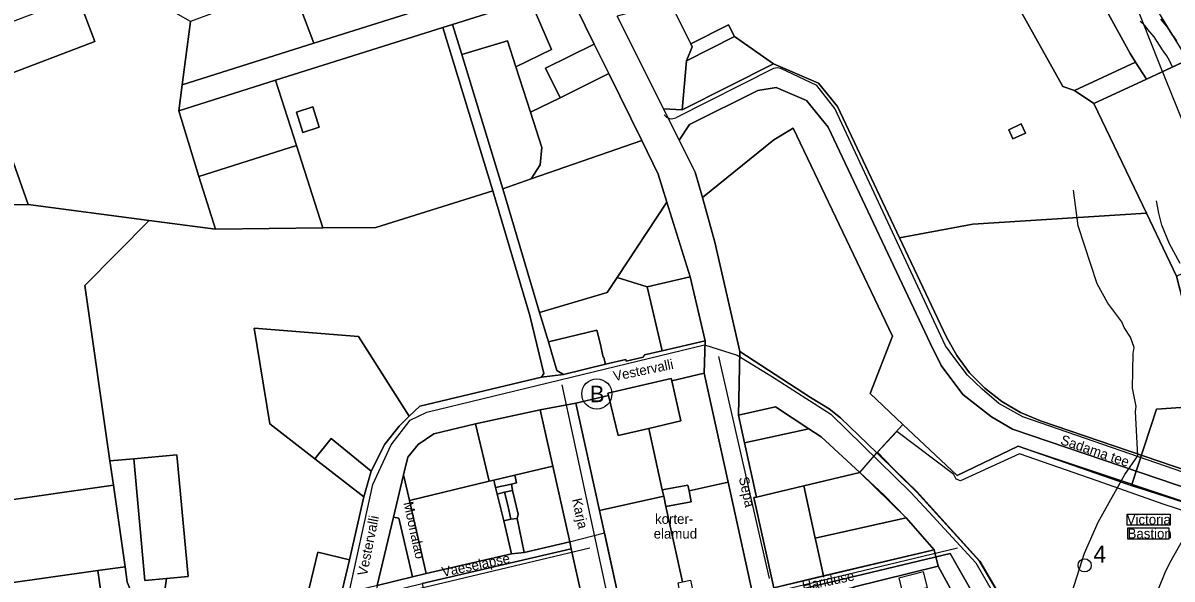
# Model space of a CAD drawing. Extents: x 728832 to 739469, y 6586263 to 6599699.
# Drawn here: x 738162 to 738859, y 6590082 to 6590420 of the extents above; entities that cross this region are included whole.
import ezdxf

# ---------------------------------------------------------------- set-up
doc = ezdxf.new("R2010")
doc.units = 0
for name, color, linetype in [('_olol_kinnismalestis', 7, 'Continuous'), ('a_kalda_ekv', 7, 'Continuous'), ('a_kalda_piiranguv', 7, 'Continuous'), ('a_kalda_veekaitsev', 7, 'Continuous'), ('a_looduskaitse_voond', 7, 'Continuous'), ('a_piir', 7, 'Continuous'), ('a_veekogu_piir', 7, 'Continuous'), ('dp_hoonestus', 7, 'Continuous'), ('PIIR', 7, 'Continuous'), ('v_dp_kehtiv', 7, 'Continuous'), ('v_dp_kontaktvoond', 7, 'Continuous'), ('v_dp_situatsioon_tekst', 7, 'Continuous'), ('v_dp_tanav_tekst', 7, 'Continuous'), ('v_dp_tekst', 7, 'Continuous'), ('v_dp_transp_bussipeatus', 7, 'Continuous'), ('v_olol_transp_jjt', 7, 'Continuous')]:
    doc.layers.add(name, color=color, linetype=linetype)

msp = doc.modelspace()

# ---------------------------------------------------------------- linework, layer by layer
at = {"layer": '_olol_kinnismalestis'}
msp.add_circle((738805.8, 6590090.62), 4, dxfattribs=at)
at = {"layer": 'a_kalda_ekv'}
for points in [[(738863.76, 6590273.78), (738857.24, 6590285.58), (738852.66, 6590296.98), (738850.77, 6590304.13), (738849.38, 6590311.72)], [(738850.77, 6590076.81), (738854.63, 6590086.37), (738857.47, 6590092.24), (738873.8, 6590121.13)]]:
    msp.add_lwpolyline(points, dxfattribs=at)
at = {"layer": 'a_kalda_piiranguv'}
msp.add_lwpolyline([(738798, 6590073.89), (738805.74, 6590098.09), (738813.94, 6590116.85), (738830.28, 6590145.74), (738838.07, 6590157), (738836.66, 6590184.02), (738837, 6590187.05), (738834.95, 6590198.11), (738835.2, 6590219.08), (738835.91, 6590222.7), (738833.64, 6590229.08), (738829.85, 6590234.96), (738828.33, 6590238.38), (738819.99, 6590249.6), (738813.47, 6590261.4), (738801.89, 6590296.47), (738798.99, 6590318.06)], dxfattribs=at)
at = {"layer": 'a_kalda_veekaitsev'}
for points in [[(738851.97, 6590421.95), (738855.98, 6590417.06), (738858.79, 6590412.67), (738861.49, 6590408.69)], [(738858.97, 6590393.1), (738857.23, 6590396.81), (738855.69, 6590399.72), (738853.45, 6590402.75), (738853.34, 6590402.9), (738853.23, 6590403.05), (738853.13, 6590403.2), (738847.92, 6590411.12), (738844.24, 6590415.6), (738842.52, 6590417.91), (738841.51, 6590418.9), (738839.59, 6590420.47)]]:
    msp.add_lwpolyline(points, dxfattribs=at)
at = {"layer": 'a_looduskaitse_voond'}
msp.add_lwpolyline([(738894.43, 6590114.34), (738853.38, 6590127.75), (738813.33, 6590141.82), (738766.33, 6590158.2), (738730.58, 6590141.98), (738727.93, 6590142.81), (738726.44, 6590145.79), (738691.85, 6590171.77), (738680.1, 6590159.36), (738689.37, 6590149.76), (738697.97, 6590141.32), (738703.93, 6590135.69), (738742.33, 6590093.16), (738753.42, 6590074.13)], dxfattribs=at)
for points in [[(738831.57, 6590121.69), (738857.79, 6590121.69), (738857.79, 6590114.98), (738831.57, 6590114.98)], [(738832.11, 6590113.33), (738856.97, 6590113.33), (738856.97, 6590106.43), (738832.11, 6590106.43)]]:
    msp.add_lwpolyline(points, close=True, dxfattribs=at)
at = {"layer": 'a_piir'}
for points in [[(738714.39, 6590648.68), (738701.09, 6590633.5), (738709.17, 6590600.23), (738724.9, 6590576.43), (738753.65, 6590521.22), (738764.74, 6590499.89), (738777.5, 6590495.02), (738782.96, 6590492.93), (738797.98, 6590465.61), (738833.44, 6590401.09), (738836.76, 6590395.87), (738843.38, 6590385.47), (738861.23, 6590393.76), (738868.42, 6590397.1), (738805.45, 6590500.11), (738796.89, 6590523.24), (738791.68, 6590528.96), (738769.71, 6590541.44), (738762.96, 6590546.51), (738751.84, 6590562.22), (738726.66, 6590613.29), (738725.19, 6590623.95)], [(738348.19, 6590560.75), (738361.16, 6590523.06), (738302.71, 6590501.98), (738324.83, 6590443.26), (738338.39, 6590407.26), (738443.88, 6590440.57), (738429.88, 6590478.4), (738419.06, 6590507.64), (738408.21, 6590535.58), (738396.36, 6590567.69), (738396.18, 6590568.2), (738392.91, 6590567.08), (738374.34, 6590560.23), (738371.16, 6590569.04)], [(738182.4, 6590516.09), (738166.83, 6590510.19), (738205.45, 6590408.26), (738139.06, 6590383.11), (738165.15, 6590309.38), (738238.5, 6590299.83), (738278.68, 6590294.6), (738268.68, 6590326.48), (738256.37, 6590366.25), (738258.43, 6590382), (738263.45, 6590420.38), (738211.78, 6590450.22), (738206.1, 6590465.17), (738201.97, 6590463.62)], [(738166.83, 6590510.19), (738153.74, 6590505.23), (738182.08, 6590430.42), (738107.28, 6590402.08), (738112.93, 6590387.16), (738139.06, 6590383.11), (738205.45, 6590408.26)], [(738658.61, 6590458.95), (738548, 6590444.85), (738554.28, 6590432.27), (738566.99, 6590406.83), (738589.9, 6590418.44), (738593.51, 6590411.34), (738617.06, 6590394.78), (738644.37, 6590383.07), (738655.92, 6590368.86), (738693.54, 6590289.26), (738738, 6590297.5), (738843.25, 6590304.19), (738811.42, 6590370.68), (738799.59, 6590378.66), (738792.6, 6590380.94), (738757.76, 6590443.5), (738743.61, 6590468.92), (738713.5, 6590459.56), (738683.62, 6590450.33), (738672.4, 6590481.35)], [(738797.98, 6590465.61), (738757.76, 6590443.5), (738792.6, 6590380.94), (738799.59, 6590378.66), (738836.76, 6590395.87), (738833.44, 6590401.09)], [(738443.88, 6590440.57), (738338.39, 6590407.26), (738258.43, 6590382), (738256.37, 6590366.25), (738315.06, 6590384.77), (738416.58, 6590416.85), (738422.48, 6590418.71), (738469.63, 6590433.6), (738491.73, 6590440.58), (738485.29, 6590453.65)], [(738263.45, 6590420.38), (738258.43, 6590382), (738338.39, 6590407.26), (738324.83, 6590443.26)], [(738469.7, 6590365.38), (738487.64, 6590374.22), (738478.8, 6590392.17), (738508.39, 6590406.75), (738491.73, 6590440.58), (738469.63, 6590433.6), (738482.43, 6590403.56), (738460.89, 6590392.94)], [(738469.63, 6590433.6), (738422.48, 6590418.71), (738428.13, 6590400.35), (738455.82, 6590408.79), (738460.89, 6590392.94), (738482.43, 6590403.56)], [(738554.28, 6590432.27), (738522.36, 6590423.74), (738550.42, 6590367.55), (738561.68, 6590366.87), (738564.37, 6590396.51), (738567.87, 6590405.02), (738566.99, 6590406.83)], [(738416.58, 6590416.85), (738315.06, 6590384.77), (738327.82, 6590345.21), (738343.89, 6590295.31), (738375.96, 6590295.57), (738446.82, 6590317.75)], [(738422.48, 6590418.71), (738416.58, 6590416.85), (738446.82, 6590317.75), (738469.35, 6590242.13), (738477.74, 6590206.88), (738476.47, 6590204.81), (738489.66, 6590206.4), (738485.74, 6590208.8), (738480.57, 6590226.15), (738475.29, 6590243.89), (738452.88, 6590319.06), (738428.13, 6590400.35)], [(738567.87, 6590405.02), (738564.37, 6590396.51), (738593.51, 6590411.34), (738589.9, 6590418.44), (738566.99, 6590406.83)], [(738455.82, 6590408.79), (738428.13, 6590400.35), (738452.88, 6590319.06), (738470.12, 6590325.05), (738475.52, 6590333.61), (738476.53, 6590344.05), (738469.7, 6590365.38), (738460.89, 6590392.94)], [(738593.51, 6590411.34), (738564.37, 6590396.51), (738561.68, 6590366.87), (738617.06, 6590394.78)], [(738508.39, 6590406.75), (738478.8, 6590392.17), (738487.64, 6590374.22), (738517.23, 6590388.81)], [(738799.59, 6590378.66), (738811.42, 6590370.68), (738843.38, 6590385.47), (738836.76, 6590395.87)], [(738868.42, 6590397.1), (738861.23, 6590393.76), (738843.38, 6590385.47), (738811.42, 6590370.68), (738843.25, 6590304.19), (738861.55, 6590265.91), (738879.95, 6590274.65), (738893.72, 6590281.43), (738909.55, 6590289.44), (738899.03, 6590318.58), (738896.01, 6590344.11), (738886.01, 6590366.86)], [(738112.93, 6590387.16), (738024.66, 6590353.6), (738028.04, 6590344.14), (738032.7, 6590309.07), (738165.15, 6590309.38), (738139.06, 6590383.11)], [(738487.64, 6590374.22), (738469.7, 6590365.38), (738476.53, 6590344.05), (738475.52, 6590333.61), (738470.12, 6590325.05), (738537.19, 6590348.31), (738517.23, 6590388.81)], [(738315.06, 6590384.77), (738256.37, 6590366.25), (738268.68, 6590326.48), (738327.82, 6590345.21)], [(738618.75, 6590380.33), (738607.64, 6590378.6), (738566.13, 6590357.93), (738559.92, 6590348.55), (738569.64, 6590329.09), (738573.98, 6590313.62), (738617.27, 6590348.72), (738629.02, 6590355.8), (738689.32, 6590229.61), (738675.68, 6590194.79), (738695.6, 6590176.04), (738728.46, 6590145.13), (738765.47, 6590163.01), (738835.3, 6590138.74), (738883.93, 6590123.77), (738901.84, 6590117.49), (738905.68, 6590124.48), (738762.03, 6590173.28), (738749.36, 6590180.65), (738732, 6590194.18), (738718.81, 6590211.81), (738712.34, 6590224.93), (738650.22, 6590356.38), (738637.19, 6590372.44)], [(738337.76, 6590368.7), (738341.61, 6590356.44), (738331.63, 6590353.22), (738327.77, 6590365.48)], [(738337.76, 6590368.7), (738327.77, 6590365.48), (738331.63, 6590353.22), (738341.61, 6590356.44)], [(738629.02, 6590355.8), (738617.27, 6590348.72), (738573.98, 6590313.62), (738581.58, 6590286.62), (738596.71, 6590220.35), (738639.48, 6590192.38), (738650.86, 6590185.59), (738657.67, 6590180.09), (738679.71, 6590158.82), (738695.6, 6590176.04), (738675.68, 6590194.79), (738689.32, 6590229.61)], [(738767.41, 6590358.32), (738769.94, 6590352.81), (738762.33, 6590349.3), (738759.8, 6590354.82)], [(738767.41, 6590358.32), (738759.8, 6590354.82), (738762.33, 6590349.3), (738769.94, 6590352.81)], [(738537.19, 6590348.31), (738470.12, 6590325.05), (738452.88, 6590319.06), (738475.29, 6590243.89), (738516.31, 6590256.12), (738522.25, 6590265.1), (738552.48, 6590310.81), (738547.27, 6590327.85)], [(738327.82, 6590345.21), (738268.68, 6590326.48), (738278.68, 6590294.6), (738343.89, 6590295.31)], [(738552.48, 6590310.81), (738522.25, 6590265.1), (738540.46, 6590259.57), (738566.52, 6590265.62)], [(738032.7, 6590309.07), (738040.91, 6590247.3), (738113.13, 6590254.89), (738126.92, 6590256.35), (738144.64, 6590129.01), (738216.77, 6590139.19), (738214.65, 6590153.96), (738199.4, 6590260.41), (738238.5, 6590299.83), (738165.15, 6590309.38)], [(738843.25, 6590304.19), (738738, 6590297.5), (738693.54, 6590289.26), (738721.83, 6590229.41), (738728.22, 6590217.92), (738736.09, 6590207.4), (738745.32, 6590197.99), (738755.65, 6590189.94), (738767, 6590183.31), (738779.12, 6590178.25), (738877.58, 6590144.8), (738893.32, 6590142.09), (738861.55, 6590265.91)], [(738475.29, 6590243.89), (738480.57, 6590226.15), (738509.9, 6590233.22), (738512.37, 6590223.66), (738512.64, 6590222.54), (738513.88, 6590216.91), (738514.14, 6590216.98), (738514.47, 6590215.73), (738515.3, 6590212.54), (738527.49, 6590215.46), (738527.83, 6590214.44), (738538.04, 6590216.8), (738538.97, 6590218.21), (738549.59, 6590220.75), (738540.46, 6590259.57), (738522.25, 6590265.1), (738516.31, 6590256.12)], [(738566.52, 6590265.62), (738540.46, 6590259.57), (738549.59, 6590220.75), (738575.69, 6590226.81)], [(738302.21, 6590234.38), (738311.66, 6590176.41), (738338.96, 6590155.24), (738348.86, 6590167.61), (738373.09, 6590147.78), (738381.42, 6590164.04), (738390.03, 6590174.98), (738396.25, 6590181.02), (738365.44, 6590229.39)], [(738480.57, 6590226.15), (738485.74, 6590208.8), (738489.66, 6590206.4), (738515.3, 6590212.54), (738514.47, 6590215.73), (738514.14, 6590216.98), (738513.88, 6590216.91), (738512.64, 6590222.54), (738512.37, 6590223.66), (738509.9, 6590233.22)], [(738589.58, 6590141.08), (738575.1, 6590207.14), (738555.43, 6590202.57), (738560.92, 6590178.21), (738541.48, 6590173.72), (738549.66, 6590136.43), (738565.23, 6590139.36), (738565.9, 6590135.88)], [(738555.11, 6590203.95), (738516.63, 6590195.01), (738516.98, 6590193.63), (738522.99, 6590169.48), (738541.48, 6590173.72), (738560.92, 6590178.21), (738555.43, 6590202.57)], [(738516.98, 6590193.63), (738497.29, 6590189.06), (738511.56, 6590123.98), (738550.51, 6590132.51), (738549.66, 6590136.43), (738541.48, 6590173.72), (738522.99, 6590169.48)], [(738475.68, 6590185.04), (738436.39, 6590176.37), (738444.7, 6590141.6), (738447.55, 6590142.28), (738460.21, 6590145.29), (738483.3, 6590150.79)], [(738497.29, 6590189.06), (738475.68, 6590185.04), (738483.3, 6590150.79), (738493.5, 6590104.86), (738494.45, 6590100.6), (738506.94, 6590044.51), (738518.66, 6589991.84), (738537.68, 6589996.96), (738527.2, 6590044.15), (738526.53, 6590055.67), (738511.56, 6590123.98)], [(738595.84, 6590181.72), (738599.55, 6590164.87), (738638.61, 6590173.49), (738618.41, 6590186.7)], [(738411.08, 6590170.49), (738401.71, 6590164.01), (738395.29, 6590156.21), (738392.76, 6590145.48), (738393.09, 6590144), (738396.31, 6590130.06), (738444.7, 6590141.6), (738436.39, 6590176.37)], [(738599.55, 6590164.87), (738606.8, 6590132.08), (738635.42, 6590138.88), (738669.48, 6590146.96), (738646.08, 6590168.61), (738638.61, 6590173.49)], [(738348.86, 6590167.61), (738338.96, 6590155.24), (738368.66, 6590132.24), (738373.09, 6590147.78)], [(738229.2, 6590155.26), (738235.84, 6590081.43), (738248.91, 6590082.61), (738262.11, 6590083.79), (738255.2, 6590157.59)], [(738229.2, 6590155.26), (738214.65, 6590153.96), (738216.77, 6590139.19), (738223.85, 6590089.7), (738225.18, 6590080.48), (738235.23, 6590056.78), (738240.59, 6590009.11), (738248.54, 6590010.01), (738244.14, 6590049.15), (738248.91, 6590082.61), (738235.84, 6590081.43)], [(738483.3, 6590150.79), (738460.21, 6590145.29), (738461.29, 6590140.75), (738458.12, 6590139.94), (738458.78, 6590135.99), (738462.24, 6590121.74), (738461.63, 6590119.11), (738465.93, 6590098.46), (738493.5, 6590104.86)], [(738392.76, 6590145.48), (738386.7, 6590119.95), (738389.92, 6590119.18), (738398.11, 6590083.61), (738406.53, 6590085.7), (738396.31, 6590130.06), (738393.09, 6590144)], [(738447.55, 6590142.28), (738448.6, 6590137.9), (738458.12, 6590139.94), (738461.29, 6590140.75), (738460.21, 6590145.29)], [(738684.3, 6590133.25), (738669.48, 6590146.96), (738635.42, 6590138.88), (738642.43, 6590107.1), (738697.62, 6590119.54)], [(738144.64, 6590129.01), (738148.59, 6590100.99), (738151.76, 6590079.67), (738207.43, 6590087.42), (738223.85, 6590089.7), (738216.77, 6590139.19)], [(738406.53, 6590085.7), (738458.25, 6590097.71), (738453.48, 6590117.6), (738449.57, 6590133.86), (738448.6, 6590137.9), (738447.55, 6590142.28), (738444.7, 6590141.6), (738396.31, 6590130.06)], [(738449.57, 6590133.86), (738454.07, 6590134.98), (738458.78, 6590135.99), (738458.12, 6590139.94), (738448.6, 6590137.9)], [(738565.23, 6590139.36), (738549.66, 6590136.43), (738550.51, 6590132.51), (738551.88, 6590126.25), (738567.17, 6590129.14), (738565.9, 6590135.88)], [(738563.12, 6590074.99), (738565.47, 6590064.21), (738604.55, 6590072.77), (738589.58, 6590141.08), (738565.9, 6590135.88), (738567.17, 6590129.14), (738551.88, 6590126.25), (738561.89, 6590080.58), (738566.78, 6590081.55), (738567.97, 6590076.01)], [(738635.42, 6590138.88), (738606.8, 6590132.08), (738605.26, 6590131.72), (738617.33, 6590077.03), (738647.48, 6590084.18), (738643.18, 6590103.72), (738642.43, 6590107.1)], [(738449.57, 6590133.86), (738453.48, 6590117.6), (738457.91, 6590118.55), (738455.92, 6590127.06), (738454.07, 6590134.98)], [(738458.78, 6590135.99), (738454.07, 6590134.98), (738455.92, 6590127.06), (738457.91, 6590118.55), (738461.63, 6590119.11), (738462.24, 6590121.74)], [(738511.56, 6590123.98), (738526.53, 6590055.67), (738565.47, 6590064.21), (738563.12, 6590074.99), (738560.38, 6590074.4), (738559.21, 6590080.04), (738561.89, 6590080.58), (738551.88, 6590126.25), (738550.51, 6590132.51)], [(738386.7, 6590119.95), (738376.82, 6590078.35), (738398.11, 6590083.61), (738389.92, 6590119.18)], [(738457.91, 6590118.55), (738453.48, 6590117.6), (738458.25, 6590097.71), (738465.93, 6590098.46), (738461.63, 6590119.11)], [(738642.43, 6590107.1), (738643.18, 6590103.72), (738647.48, 6590084.18), (738714.48, 6590100.13), (738697.62, 6590119.54)], [(738493.5, 6590104.86), (738465.93, 6590098.46), (738458.25, 6590097.71), (738406.53, 6590085.7), (738398.11, 6590083.61), (738376.82, 6590078.35), (738376.03, 6590072.69), (738404.03, 6590079.58), (738494.45, 6590100.6)], [(738340.83, 6590098.65), (738330.23, 6590054.91), (738322.84, 6590056.7), (738319.39, 6590042.48), (738305.89, 6590040.45), (738309.1, 6590016.77), (738342.45, 6590020.49), (738360.01, 6590094.01)], [(738404.03, 6590079.58), (738415.18, 6590029.35), (738416.49, 6590023.5), (738506.94, 6590044.51), (738494.45, 6590100.6)], [(738714.48, 6590100.13), (738647.48, 6590084.18), (738617.33, 6590077.03), (738617.39, 6590065.7), (738656.06, 6590075.17), (738665.48, 6590077.48), (738716.96, 6590090.08)], [(738207.43, 6590087.42), (738151.76, 6590079.67), (738162.79, 6590000.44), (738183.85, 6590002.79), (738179.09, 6590036.17), (738211.08, 6590039.58), (738211.99, 6590044.06), (738213.43, 6590044.22)], [(738223.85, 6590089.7), (738207.43, 6590087.42), (738213.43, 6590044.22), (738211.99, 6590044.06), (738211.08, 6590039.58), (738179.09, 6590036.17), (738183.85, 6590002.79), (738240.59, 6590009.11), (738235.23, 6590056.78), (738225.18, 6590080.48)], [(738716.96, 6590090.08), (738665.48, 6590077.48), (738676.92, 6590033.37), (738738.99, 6590049.61)]]:
    msp.add_lwpolyline(points, close=True, dxfattribs=at)
for points in [[(738491.73, 6590440.58), (738508.39, 6590406.75), (738517.23, 6590388.81), (738537.19, 6590348.31), (738547.27, 6590327.85), (738552.48, 6590310.81), (738566.52, 6590265.62), (738575.69, 6590226.81), (738575.1, 6590207.14), (738589.58, 6590141.08), (738604.55, 6590072.77)], [(738617.33, 6590077.03), (738605.26, 6590131.72), (738606.8, 6590132.08), (738599.55, 6590164.87), (738595.84, 6590181.72), (738596.71, 6590220.35), (738581.58, 6590286.62), (738573.98, 6590313.62), (738569.64, 6590329.09), (738559.92, 6590348.55), (738550.42, 6590367.55), (738522.36, 6590423.74)], [(738877.58, 6590144.8), (738779.12, 6590178.25), (738767, 6590183.31), (738755.65, 6590189.94), (738745.32, 6590197.99), (738736.09, 6590207.4), (738728.22, 6590217.92), (738721.83, 6590229.41), (738693.54, 6590289.26), (738655.92, 6590368.86), (738644.37, 6590383.07), (738617.06, 6590394.78), (738561.68, 6590366.87), (738550.42, 6590367.55), (738559.92, 6590348.55), (738566.13, 6590357.93), (738607.64, 6590378.6), (738618.75, 6590380.33), (738637.19, 6590372.44), (738650.22, 6590356.38), (738712.34, 6590224.93), (738718.81, 6590211.81), (738732, 6590194.18), (738749.36, 6590180.65), (738762.03, 6590173.28), (738905.68, 6590124.48)], [(738330.23, 6590054.91), (738340.83, 6590098.65), (738360.01, 6590094.01), (738368.66, 6590132.24), (738338.96, 6590155.24), (738311.66, 6590176.41), (738302.21, 6590234.38), (738365.44, 6590229.39), (738396.25, 6590181.02), (738402.57, 6590187.17), (738476.47, 6590204.81), (738477.74, 6590206.88), (738469.35, 6590242.13), (738446.82, 6590317.75), (738375.96, 6590295.57), (738343.89, 6590295.31), (738278.68, 6590294.6), (738238.5, 6590299.83), (738199.4, 6590260.41), (738214.65, 6590153.96), (738229.2, 6590155.26), (738255.2, 6590157.59), (738262.11, 6590083.79), (738248.91, 6590082.61), (738244.14, 6590049.15)], [(738376.82, 6590078.35), (738386.7, 6590119.95), (738392.76, 6590145.48), (738395.29, 6590156.21), (738401.71, 6590164.01), (738411.08, 6590170.49), (738436.39, 6590176.37), (738475.68, 6590185.04), (738497.29, 6590189.06), (738516.98, 6590193.63), (738516.63, 6590195.01), (738555.11, 6590203.95), (738555.43, 6590202.57), (738575.1, 6590207.14), (738575.69, 6590226.81), (738549.59, 6590220.75), (738538.97, 6590218.21), (738538.04, 6590216.8), (738527.83, 6590214.44), (738527.49, 6590215.46), (738515.3, 6590212.54), (738489.66, 6590206.4), (738476.47, 6590204.81), (738402.57, 6590187.17), (738396.25, 6590181.02), (738390.03, 6590174.98), (738381.42, 6590164.04), (738373.09, 6590147.78), (738368.66, 6590132.24), (738360.01, 6590094.01), (738342.45, 6590020.49)], [(738764.49, 6590055.06), (738742.13, 6590093.07), (738704.08, 6590135.11), (738679.71, 6590158.82), (738657.67, 6590180.09), (738650.86, 6590185.59), (738639.48, 6590192.38), (738596.71, 6590220.35), (738595.84, 6590181.72), (738618.41, 6590186.7), (738638.61, 6590173.49), (738646.08, 6590168.61), (738669.48, 6590146.96), (738684.3, 6590133.25), (738697.62, 6590119.54), (738714.48, 6590100.13), (738716.96, 6590090.08), (738738.99, 6590049.61)], [(738883.93, 6590123.77), (738835.3, 6590138.74), (738765.47, 6590163.01), (738728.46, 6590145.13), (738695.6, 6590176.04), (738679.71, 6590158.82), (738704.08, 6590135.11), (738742.13, 6590093.07), (738764.49, 6590055.06)]]:
    msp.add_lwpolyline(points, dxfattribs=at)
at = {"layer": 'a_veekogu_piir'}
msp.add_lwpolyline([(738861.49, 6590408.69), (738858.79, 6590412.67), (738855.98, 6590417.06), (738851.97, 6590421.95)], dxfattribs=at)
at = {"layer": 'dp_hoonestus'}
msp.add_lwpolyline([(738865.96, 6590358.13), (738851.06, 6590395.2), (738836.17, 6590432.44)], dxfattribs=at)
msp.add_lwpolyline([(738865.96, 6590358.13), (738851.06, 6590395.2), (738836.17, 6590432.44)], dxfattribs=at)
at = {"layer": 'PIIR'}
msp.add_lwpolyline([(738708.09, 6590086.74), (738693.18, 6590082.96), (738695.63, 6590073.33), (738698.86, 6590074.15), (738702.99, 6590056.62), (738687.18, 6590052.74), (738689.75, 6590041.1), (738715.46, 6590047.27), (738708.43, 6590076.77), (738710.46, 6590077.18)], close=True, dxfattribs=at)
at = {"layer": 'v_dp_kehtiv'}
for points in [[(738834.26, 6590139.1), (738901.84, 6590117.49), (738833.77, 6589993.69), (738849.37, 6589989.36), (738911.94, 6589971.59), (738937.72, 6590021.18), (738984.2, 6590114.69), (738993.34, 6590247.02), (738942.21, 6590350.94), (738908.53, 6590414.77), (738868.42, 6590397.1), (738843.38, 6590385.47), (738811.42, 6590370.68), (738843.25, 6590304.19), (738861.55, 6590265.91), (738881.66, 6590187.51), (738849.36, 6590185.31)], [(738833.77, 6589993.69), (738901.84, 6590117.49), (738834.26, 6590139.1), (738849.36, 6590185.31), (738881.66, 6590187.51), (738861.55, 6590265.91), (738843.25, 6590304.19), (738811.42, 6590370.68), (738868.42, 6590397.1), (738908.53, 6590414.77), (738942.21, 6590350.94), (738993.34, 6590247.02), (738984.2, 6590114.69), (738937.72, 6590021.18), (738911.94, 6589971.59), (738869.57, 6589983.62), (738849.37, 6589989.36)], [(738518.28, 6590048.41), (738724.34, 6590097.89), (738754.16, 6590045.25), (738560.05, 6589994.65), (738532.9, 6589987.47)], [(738518.28, 6590048.41), (738532.9, 6589987.47), (738560.05, 6589994.65), (738754.16, 6590045.25), (738724.34, 6590097.89)]]:
    msp.add_lwpolyline(points, close=True, dxfattribs=at)
at = {"layer": 'v_dp_kontaktvoond'}
for points in [[(738617.36, 6590077.07), (738714.48, 6590100.13), (738697.62, 6590119.54), (738669.48, 6590146.96), (738679.81, 6590158.86), (738695.6, 6590176.04), (738728.46, 6590145.13), (738765.47, 6590163.01), (738901.84, 6590117.49)], [(738355.08, 6590073.37), (738398.07, 6590083.62), (738406.54, 6590085.71), (738458.3, 6590097.77), (738465.94, 6590098.46), (738493.38, 6590104.99), (738514.55, 6590110.32), (738526.53, 6590055.67)]]:
    msp.add_lwpolyline(points, dxfattribs=at)
at = {"layer": 'v_dp_transp_bussipeatus'}
msp.add_circle((738509.98, 6590194.58), 9.17, dxfattribs=at)
at = {"layer": 'v_olol_transp_jjt'}
for p, q in [((738614.66, 6590082.58), (738583.87, 6590217.2)), ((738362.91, 6590067.21), (738505.73, 6590101.28)), ((738520.62, 6590051.41), (738728.63, 6590101.35))]:
    msp.add_line(p, q, dxfattribs=at)
for points in [[(738617.22, 6590391.85), (738617.22, 6590391.85), (738557.93, 6590362.08)], [(738913.83, 6590122.24), (738912.56, 6590132.76), (738893.48, 6590139.7), (738881.68, 6590141.55), (738768.41, 6590180.71), (738753.8, 6590188.84), (738743.64, 6590197.42), (738734.87, 6590206), (738726.51, 6590216.87), (738721.42, 6590223.76), (738654.4, 6590367.7), (738643.42, 6590381.67), (738621.61, 6590391.85)], [(738347.8, 6590019.69), (738363.94, 6590093.67), (738374.1, 6590139.65), (738385.3, 6590163.74), (738396.83, 6590178.71), (738406.79, 6590183.43), (738575.2, 6590224.32), (738595.13, 6590218.05), (738616.46, 6590204.89), (738651.98, 6590182.26), (738700.49, 6590134.84), (738711.25, 6590123.1), (738739.83, 6590092.1), (738762.58, 6590052.49)], [(738514.15, 6590045.17), (738517.89, 6590065.8), (738489.02, 6590200.03)]]:
    msp.add_lwpolyline(points, dxfattribs=at)
for centre, radius, start, end in [((738619.41, 6590387.36), 5, 63.87656, 115.95005), ((738555.41, 6590367.23), 5.73, 217.48647, 296.08847)]:
    msp.add_arc(centre, radius, start, end, dxfattribs=at)

# ---------------------------------------------------------------- texts
at = {"layer": '_olol_kinnismalestis'}
msp.add_text('4', height=10.4, dxfattribs=at).set_placement((738811.13, 6590092.27))
at = {"layer": 'v_dp_situatsioon_tekst'}
for s, p in [('Victoria', (738831.34, 6590115.4)), ('Bastion', (738831.87, 6590106.92))]:
    msp.add_text(s, height=6, dxfattribs=at).set_placement(p)
at = {"layer": 'v_dp_tanav_tekst'}
for s, rotation, p in [('Vestervalli', 11.84023, (738520.63, 6590202.32)), ('Sadama tee', 341.07954, (738790.7, 6590164.27)), ('Sepa', 282.3431, (738596.04, 6590143.7)), ('Karja', 282.3431, (738494.87, 6590130.65)), ('Moonalao', 282.3431, (738392.64, 6590128.55)), ('Vestervalli', 78.5375, (738370.52, 6590083.87)), ('Vaeselapse', 11.84023, (738416.67, 6590083.58)), ('Hariduse', 11.84023, (738635.17, 6590075.05))]:
    msp.add_text(s, height=6, rotation=rotation, dxfattribs=at).set_placement(p)
at = {"layer": 'v_dp_tekst'}
for s, p in [('korter-', (738545.27, 6590115.79)), ('elamud', (738544.45, 6590106.88))]:
    msp.add_text(s, height=6, dxfattribs=at).set_placement(p)
at = {"layer": 'v_dp_transp_bussipeatus'}
msp.add_text('B', height=10, dxfattribs=at).set_placement((738505.69, 6590189.58))

doc.saveas('drawing.dxf')
